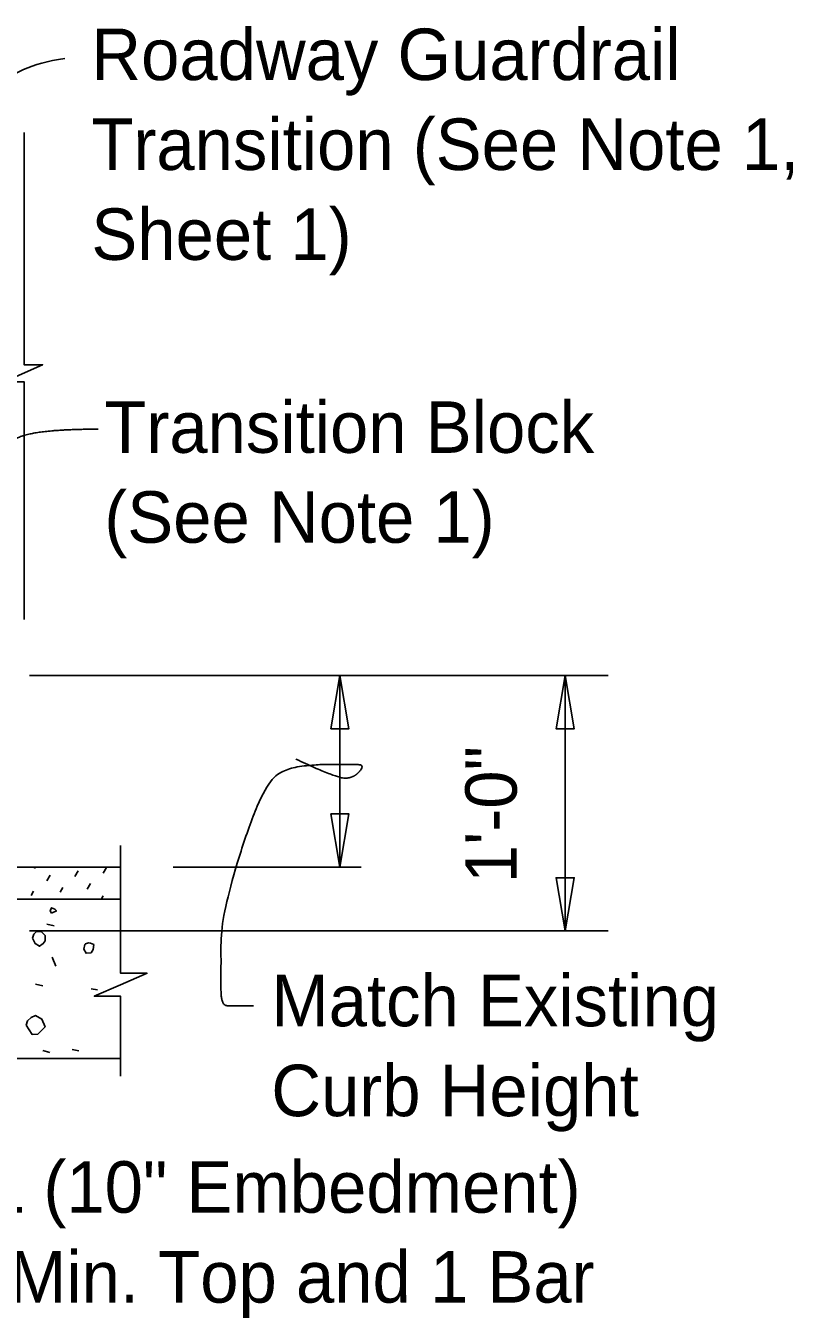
# Model space of a CAD drawing. Extents: x 21587 to 21659.1, y 56113.9 to 56155.9.
# Drawn here: x 21623.99 to 21626.99, y 56132.28 to 56137.34 of the extents above; entities that cross this region are included whole.
import ezdxf

# ---------------------------------------------------------------- set-up
doc = ezdxf.new("R2010")
doc.units = 0
for name, color, linetype in [('AdhocPoint_dp', 7, 'Continuous'), ('PlotBorder_dp', 7, 'Continuous'), ('SheetBorder_dp', 7, 'Continuous'), ('TextMisc', 7, 'Continuous')]:
    doc.layers.add(name, color=color, linetype=linetype)

msp = doc.modelspace()

# ---------------------------------------------------------------- linework, layer by layer
at = {"layer": 'AdhocPoint_dp'}
for p, q in [((21624.3563, 56134.0511), (21613.608, 56134.0511)), ((21622.1027, 56133.926), (21624.3563, 56133.926)), ((21624.3563, 56133.301), (21618.8279, 56133.301))]:
    msp.add_line(p, q, dxfattribs=at)
at = {"layer": 'PlotBorder_dp'}
for p, q in [((21623.9999, 56134.8009), (21626.2654, 56134.8009)), ((21625.2148, 56134.8009), (21625.2148, 56134.0509)), ((21626.0969, 56134.801), (21626.0969, 56133.801)), ((21624.5621, 56134.0509), (21625.2975, 56134.0509)), ((21623.9999, 56133.8009), (21626.2654, 56133.8009))]:
    msp.add_line(p, q, dxfattribs=at)
for points in [[(21623.978, 56135.0198), (21623.978, 56135.9514), (21623.9005, 56135.9514), (21624.0505, 56136.0177), (21623.978, 56136.0177), (21623.978, 56136.9265)], [(21624.3563, 56133.233), (21624.3563, 56133.5455), (21624.253, 56133.5455), (21624.3563, 56133.5905), (21624.4596, 56133.6355), (21624.3563, 56133.6355), (21624.3563, 56134.1353)]]:
    msp.add_lwpolyline(points, dxfattribs=at)
for points in [[(21625.2148, 56134.8009), (21625.1795, 56134.5927), (21625.2501, 56134.5927)], [(21626.0969, 56134.801), (21626.0616, 56134.5928), (21626.1322, 56134.5928)], [(21625.2148, 56134.0509), (21625.2501, 56134.2592), (21625.1795, 56134.2592)], [(21626.0969, 56133.801), (21626.1322, 56134.0093), (21626.0616, 56134.0093)]]:
    msp.add_lwpolyline(points, close=True, dxfattribs=at)
for points, degree in [([(21624.1376, 56137.2163), (21624.0032, 56137.199), (21623.8663, 56137.1171), (21623.7028, 56136.9653), (21623.4907, 56136.7744)], 3), ([(21624.2687, 56135.7655), (21624.0532, 56135.7655), (21623.8906, 56135.7125), (21623.6609, 56135.412), (21623.4241, 56134.8039)], 2), ([(21624.8766, 56133.5082), (21624.7988, 56133.5082), (21624.7493, 56133.5082), (21624.7493, 56133.6284), (21624.7493, 56133.8724), (21624.919, 56134.3956), (21625.0533, 56134.4522), (21625.2547, 56134.4522), (21625.3148, 56134.4522), (21625.2688, 56134.3991), (21625.2017, 56134.3991), (21625.0427, 56134.4734)], 2)]:
    msp.add_open_spline(points, degree=degree, dxfattribs=at)
at = {"layer": 'TextMisc'}
for p, q in [((21624.0189, 56134.0456), (21624.022, 56134.0511)), ((21624.0677, 56133.9968), (21624.0807, 56134.0192)), ((21624.1771, 56134.0136), (21624.19, 56134.036)), ((21624.2877, 56134.0266), (21624.3007, 56134.049)), ((21624.0058, 56133.9392), (21624.0157, 56133.9563)), ((21624.1196, 56133.9533), (21624.1295, 56133.9704)), ((21624.2259, 56133.9648), (21624.2389, 56133.9872)), ((21624.1764, 56133.9243), (21624.1771, 56133.9254)), ((21624.2796, 56133.9243), (21624.2877, 56133.9383)), ((21624.0678, 56133.8276), (21624.0961, 56133.8206)), ((21624.1027, 56133.6624), (21624.0886, 56133.6978)), ((21624.0232, 56133.5932), (21624.0515, 56133.5862)), ((21624.2406, 56133.574), (21624.2653, 56133.5705)), ((21624.0513, 56133.3324), (21624.0796, 56133.3254)), ((21624.1663, 56133.3371), (21624.1928, 56133.3318))]:
    msp.add_line(p, q, dxfattribs=at)
for points in [[(21624.0858, 56133.8707), (21624.1052, 56133.8796), (21624.0982, 56133.8866), (21624.0858, 56133.8919), (21624.0805, 56133.8796), (21624.0858, 56133.8707)], [(21624.011, 56133.7727), (21624.0216, 56133.7515), (21624.0393, 56133.7409), (21624.0534, 56133.7515), (21624.0605, 56133.7621), (21624.0605, 56133.7833), (21624.0446, 56133.7993), (21624.0251, 56133.7975), (21624.0163, 56133.7886), (21624.011, 56133.7727)], [(21624.2123, 56133.7296), (21624.2211, 56133.7137), (21624.2406, 56133.7155), (21624.2494, 56133.7278), (21624.2512, 56133.7473), (21624.2388, 56133.7526), (21624.23, 56133.7543), (21624.2194, 56133.7508), (21624.2158, 56133.7473), (21624.2123, 56133.7296)], [(21623.9865, 56133.4326), (21624.0095, 56133.3955), (21624.0325, 56133.3972), (21624.0413, 56133.4061), (21624.0607, 56133.4255), (21624.0484, 56133.4556), (21624.0236, 56133.4697), (21624.0059, 56133.4627), (21623.9918, 56133.4485), (21623.9865, 56133.4326)]]:
    msp.add_lwpolyline(points, dxfattribs=at)

# ---------------------------------------------------------------- texts
at = {"layer": 'PlotBorder_dp'}
for s, p in [('Roadway Guardrail ', (21624.2417, 56137.1323)), ('Transition (See Note 1, ', (21624.2417, 56136.7803)), ('Sheet 1)', (21624.2417, 56136.4283)), ('Transition Block', (21624.2925, 56135.6728)), ('(See Note 1)', (21624.2925, 56135.3208)), ('Match Existing ', (21624.9463, 56133.4277)), ('Curb Height', (21624.9463, 56133.0757)), ('Dowel Bars 4L (10" Embedment) ', (21622.226, 56132.6977)), ('(Place 3 Bars Min. Top and 1 Bar ', (21622.226, 56132.3457))]:
    msp.add_text(s, height=0.2016, dxfattribs=at).set_placement(p)
at = {"layer": 'SheetBorder_dp'}
msp.add_text('1\'-0"', height=0.2016, rotation=90, dxfattribs=at).set_placement((21625.9073, 56133.9882))

doc.saveas('drawing.dxf')
